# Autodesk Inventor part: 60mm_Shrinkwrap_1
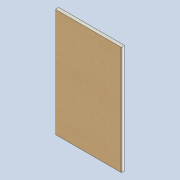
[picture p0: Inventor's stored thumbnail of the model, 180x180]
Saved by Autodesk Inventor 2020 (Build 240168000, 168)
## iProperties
Created: 2020-11
Part Number: 60mm_Shrinkwrap_1
Material: Generic
Document SubType Name: Modeling
Designer: Yolande
Density: 1 g/cm^3
Appearance: Default
Author: Yolande
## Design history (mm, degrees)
derived "60mm.iam"
body "Solid1"
node "Lambdaboard 60mm Kraft.ipt:1" dims "d0" = 10
